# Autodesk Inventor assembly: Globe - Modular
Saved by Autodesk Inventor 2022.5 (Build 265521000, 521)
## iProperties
Created: 2025-01
Part Number: Globe - Modular
Document SubType Name: Assembly
Designer: AdminForWorker
Title: Globe - Modular v9
Author: AdminForWorker
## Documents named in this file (4)
- c:\worker\convert-fusion-r06-cosv3\tmp\job-1\29\temp\files\f49780df-0694-4984-a1ae-57f0d39a4680\2492528c-5afb-4d90-b883-9a497b699368.iam
- c:\worker\convert-fusion-r06-cosv3\tmp\job-1\29\temp\files\f49780df-0694-4984-a1ae-57f0d39a4680\Solitaire Pettie Modular.ipt
- c:\worker\convert-fusion-r06-cosv3\tmp\job-1\29\temp\files\f49780df-0694-4984-a1ae-57f0d39a4680\Modular - Placebo - Bayonet Connector v4.ipt
- c:\worker\convert-fusion-r06-cosv3\tmp\job-1\29\temp\files\f49780df-0694-4984-a1ae-57f0d39a4680\Modular - Placedo - Cord Set v4.ipt
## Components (3 placed, 3 different names)
1. Solitaire Pettie Modular:1
2. Modular - Placebo - Bayonet Connector v4:1
3. Modular - Placedo - Cord Set v4:1
